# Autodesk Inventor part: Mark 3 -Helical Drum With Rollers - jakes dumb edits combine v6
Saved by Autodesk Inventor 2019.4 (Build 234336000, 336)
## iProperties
Created: 2020-06
Part Number: Mark 3 -Helical Drum With Rollers - jakes dumb edits combine v6
Material: Generic
Document SubType Name: Modeling
Designer: Administrator
Density: 1 g/cm^3
Appearance: Default
Author: Administrator
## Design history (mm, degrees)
feature "Main Body (1)"
body "Solid1"
